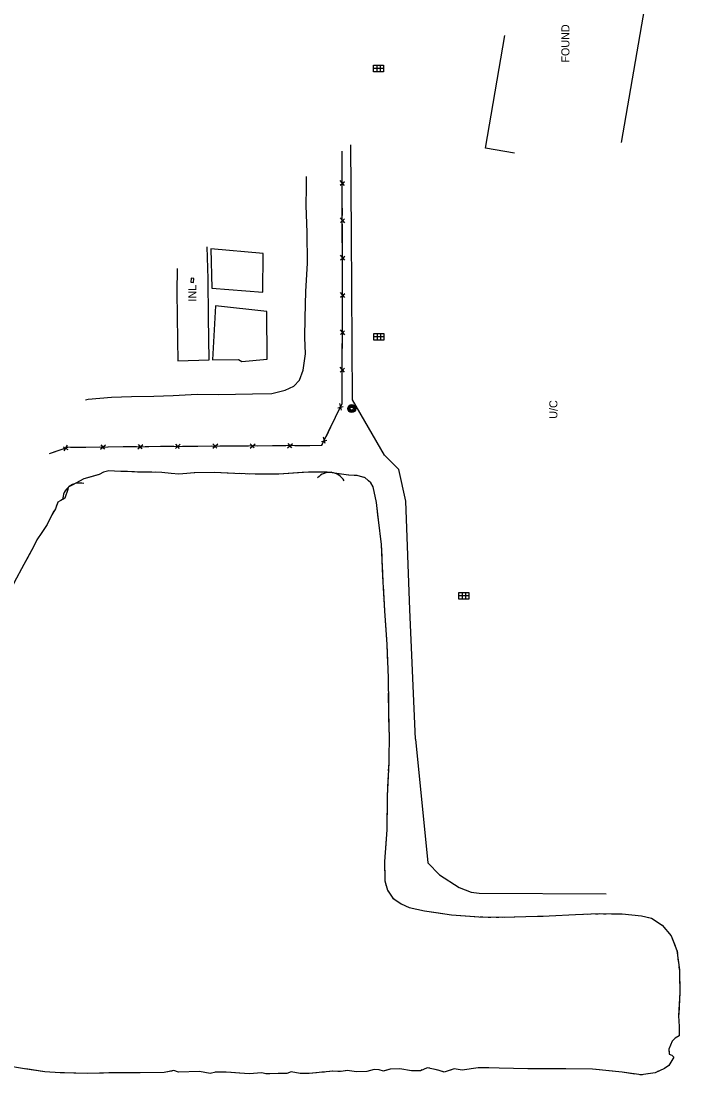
# Model space of a CAD drawing. Extents: x 588843 to 2552415, y 180129 to 269402.
# Drawn here: x 592942 to 593434, y 186354 to 187140 of the extents above; entities that cross this region are included whole.
import ezdxf

# ---------------------------------------------------------------- set-up
doc = ezdxf.new("R2010")
doc.units = 0
for name, color, linetype in [('E_DRN', 7, 'Continuous'), ('E_DRN_PipePlastic', 7, 'Continuous'), ('E_DRN_PipeRein', 7, 'Continuous'), ('Level 12', 7, 'Continuous'), ('Level 15', 7, 'Continuous'), ('Level 16', 7, 'Continuous'), ('Level 17', 7, 'Continuous'), ('Level 19', 7, 'Continuous')]:
    doc.layers.add(name, color=color, linetype=linetype)

msp = doc.modelspace()

# ---------------------------------------------------------------- linework, layer by layer
at = {"layer": 'E_DRN'}
for p, q in [((593205.24, 187101.86), (593205.24, 187106.86)), ((593205.24, 187106.86), (593212.74, 187106.86)), ((593212.74, 187104.36), (593205.24, 187104.36)), ((593207.74, 187106.86), (593207.74, 187101.86)), ((593210.24, 187106.86), (593210.24, 187101.86)), ((593212.74, 187106.86), (593212.74, 187101.86)), ((593212.74, 187101.86), (593205.24, 187101.86)), ((593208.99, 187101.86), (593208.99, 187101.86)), ((593205.52, 186901.87), (593205.52, 186906.87)), ((593205.52, 186906.87), (593213.02, 186906.87)), ((593208.02, 186906.87), (593208.02, 186901.87)), ((593210.52, 186906.87), (593210.52, 186901.87)), ((593213.02, 186906.87), (593213.02, 186901.87)), ((593213.02, 186904.37), (593205.52, 186904.37)), ((593213.02, 186901.87), (593205.52, 186901.87)), ((593209.27, 186901.87), (593209.27, 186901.87)), ((593268.89, 186708.85), (593268.89, 186713.85)), ((593268.89, 186713.85), (593276.39, 186713.85)), ((593276.39, 186711.35), (593268.89, 186711.35)), ((593271.39, 186713.85), (593271.39, 186708.85)), ((593273.89, 186713.85), (593273.89, 186708.85)), ((593276.39, 186713.85), (593276.39, 186708.85)), ((593276.39, 186708.85), (593268.89, 186708.85)), ((593272.64, 186708.85), (593272.64, 186708.85))]:
    msp.add_line(p, q, dxfattribs=at)
at = {"layer": 'E_DRN_PipePlastic'}
for p, q in [((593192.67, 186800.85), (593192.67, 186800.85)), ((593211.66, 186709.2), (593211.66, 186709.2))]:
    msp.add_line(p, q, dxfattribs=at)
at = {"layer": 'E_DRN_PipeRein'}
msp.add_line((593174.13, 186804.34), (593174.13, 186804.34), dxfattribs=at)
at = {"layer": 'Level 12'}
for points in [[(593417.75, 187210.51), (593389.9, 187049.22)], [(593310.3, 187041.33), (593288.69, 187045.06), (593303.2, 187129.12)]]:
    msp.add_lwpolyline(points, dxfattribs=at)
at = {"layer": 'Level 15'}
for p, q in [((593183.67, 187017.33), (593180.43, 187021.04)), ((593180.43, 187017.49), (593183.6, 187020.29)), ((593183.74, 186989.47), (593180.49, 186993.18)), ((593180.5, 186989.63), (593183.66, 186992.44)), ((593183.81, 186961.61), (593180.56, 186965.32)), ((593180.57, 186961.77), (593183.73, 186964.58)), ((593183.87, 186933.74), (593180.64, 186937.47)), ((593180.63, 186933.92), (593183.81, 186936.71)), ((593180.52, 186906.06), (593183.7, 186908.85)), ((593183.75, 186905.88), (593180.53, 186909.61)), ((593180.4, 186878.2), (593183.58, 186880.99)), ((593183.64, 186878.02), (593180.42, 186881.75)), ((593178.55, 186851.43), (593182.62, 186852.57)), ((593181.39, 186849.86), (593180.09, 186854.62)), ((593166.41, 186826.35), (593170.48, 186827.49)), ((593169.25, 186824.79), (593167.96, 186829.54)), ((592973.78, 186822.49), (592977.45, 186820.41)), ((592974.63, 186819.4), (592977.17, 186823.62)), ((593001.79, 186820.67), (593005.47, 186823.94)), ((593001.93, 186823.9), (593004.76, 186820.76)), ((593029.65, 186820.95), (593033.33, 186824.23)), ((593029.78, 186824.19), (593032.61, 186821.05)), ((593057.5, 186821.16), (593061.2, 186824.42)), ((593057.65, 186824.4), (593060.46, 186821.24)), ((593085.36, 186821.33), (593089.06, 186824.59)), ((593085.51, 186824.57), (593088.33, 186821.41)), ((593113.22, 186821.5), (593116.92, 186824.76)), ((593113.37, 186824.74), (593116.18, 186821.58)), ((593141.08, 186821.67), (593144.78, 186824.93)), ((593141.23, 186824.91), (593144.04, 186821.76))]:
    msp.add_line(p, q, dxfattribs=at)
for points in [[(592963.59, 186817.4), (592977.39, 186822.15), (593037.81, 186822.77), (593166.73, 186823.57), (593181.81, 186854.73), (593182.14, 186936.47), (593181.94, 187012.29), (593181.89, 187042.93)], [(593181.9, 187034.07), (593181.89, 187042.93)], [(593181.92, 187022.75), (593181.9, 187034.07)], [(593181.96, 187006.21), (593181.94, 187012.29), (593181.93, 187016.17)], [(593181.98, 186994.89), (593181.96, 187006.21)], [(593182.03, 186978.35), (593182, 186988.31)], [(593182.06, 186967.03), (593182.03, 186978.35)], [(593182.1, 186950.49), (593182.07, 186960.45)], [(593071.18, 186948), (593069.18, 186948.08), (593069.06, 186945.08), (593071.06, 186945), (593071.18, 186948)], [(593182.13, 186939.17), (593182.1, 186950.49)], [(593182.08, 186922.63), (593182.12, 186932.59)], [(593182.04, 186911.31), (593182.08, 186922.63)], [(593181.97, 186894.77), (593182.01, 186904.73)], [(593181.93, 186883.45), (593181.97, 186894.77)], [(593181.86, 186866.91), (593181.9, 186876.87)], [(593181.81, 186855.59), (593181.86, 186866.91)], [(593174.98, 186840.61), (593179.32, 186849.58)], [(593170.05, 186830.43), (593174.98, 186840.61)], [(592963.59, 186817.4), (592973.01, 186820.64)], [(592979.33, 186822.17), (592990.66, 186822.29)], [(592990.66, 186822.29), (593000.61, 186822.39)], [(593007.19, 186822.46), (593018.51, 186822.58)], [(593018.51, 186822.58), (593028.47, 186822.68)], [(593035.05, 186822.75), (593037.81, 186822.77), (593046.37, 186822.83)], [(593046.37, 186822.83), (593056.33, 186822.89)], [(593062.91, 186822.93), (593074.23, 186823)], [(593074.23, 186823), (593084.19, 186823.06)], [(593090.77, 186823.1), (593102.09, 186823.17)], [(593102.09, 186823.17), (593112.05, 186823.23)], [(593118.63, 186823.27), (593129.95, 186823.34)], [(593129.95, 186823.34), (593139.91, 186823.4)], [(593146.49, 186823.44), (593157.81, 186823.51)], [(593157.81, 186823.51), (593166.73, 186823.57), (593167.18, 186824.5)]]:
    msp.add_lwpolyline(points, dxfattribs=at)
for centre, start, end in [((593172.56, 186790.78), 29.98007, 136.21963), ((592985.97, 186782.95), 74.38032, 180.61989)]:
    msp.add_arc(centre, 12.5, start, end, dxfattribs=at)
at = {"layer": 'Level 16'}
for centre, radius in [((593188.99, 186850.91), 3), ((593188.99, 186850.91), 2.43), ((593188.98, 186850.88), 1.94), ((593188.93, 186850.87), 1.21)]:
    msp.add_circle(centre, radius, dxfattribs=at)
at = {"layer": 'Level 17'}
for points in [[(593236.56, 186604.57), (593232.23, 186701.05), (593229.21, 186781.81), (593224.03, 186805.6), (593213.35, 186816.17), (593189.6, 186857.42), (593188.88, 186981.32), (593188.27, 187047.46)], [(592990.42, 186857.43), (592992.54, 186857.9), (593009.9, 186859.52), (593024.84, 186859.98), (593041.36, 186860.14), (593055.85, 186860.73), (593073.84, 186861.57), (593089.58, 186861.5), (593115.05, 186862.03), (593129.37, 186862.17), (593139.27, 186864.57), (593145.93, 186867.69), (593149.94, 186872.24), (593152.8, 186879.52), (593154.48, 186891.67), (593154.05, 186903.98), (593154.38, 186918.67), (593154.81, 186938.29), (593155.99, 186959.28), (593155.71, 186982.25), (593154.96, 187002.3), (593155.23, 187015.75), (593155.17, 187023.94)], [(593058.73, 186955.42), (593058.71, 186937.78), (593059.01, 186901.83), (593059.46, 186886.51), (593082.72, 186887.2), (593082.32, 186918.9), (593081.87, 186947.63), (593081.24, 186971.41)], [(593084.69, 186940.68), (593122.75, 186937.61), (593122.84, 186966.61), (593083.99, 186970.05), (593084.69, 186940.68)], [(593085.17, 186887.24), (593104.68, 186887.55), (593107.1, 186886.13), (593125.9, 186887.8), (593125.67, 186923.22), (593087.52, 186927.64), (593085.17, 186887.24)], [(593236.56, 186604.57), (593245.76, 186512.24), (593254.4, 186503.26), (593269.01, 186493.96), (593277.98, 186490.3), (593283.96, 186489.63), (593378.71, 186489.09)]]:
    msp.add_lwpolyline(points, dxfattribs=at)
at = {"layer": 'Level 19'}
for points in [[(593216.86, 186609.81), (593216.32, 186650.11), (593215.3, 186675.06), (593213.71, 186700.12), (593212.25, 186726.11), (593211.2, 186749.52), (593208.96, 186767.97), (593207.37, 186781.01), (593204.86, 186792.6), (593203.23, 186795.53), (593199.06, 186799.33), (593192.99, 186801.04), (593186.45, 186801.32), (593177.78, 186802.54), (593170.76, 186803.62), (593156.87, 186803.62), (593134.52, 186802.04), (593117.29, 186802.02), (593101.88, 186802.53), (593086.65, 186803.22), (593071.63, 186802.94), (593065.95, 186802.46), (593060.14, 186802.15), (593054.48, 186802.59), (593047.5, 186803.38), (593039.95, 186803.43), (593029.4, 186803.56), (593021.84, 186804.03), (593016.93, 186803.93), (593012.17, 186804.27), (593007.83, 186804.54), (593003.86, 186803.43), (593000.7, 186801.89), (592989.31, 186798.53), (592980.58, 186793.78), (592977.68, 186792.4), (592977.36, 186790.49), (592975.05, 186784.07), (592969.98, 186781.15), (592968.03, 186776.23), (592965.54, 186771.75), (592961.84, 186764.5), (592957.97, 186758.51), (592954.27, 186753.11), (592951.88, 186748.48), (592944.56, 186734.79), (592937.33, 186721.35)], [(593021.09, 186804.02), (593016.93, 186803.93), (593012.17, 186804.27), (593007.83, 186804.54), (593003.86, 186803.43), (593000.7, 186801.89), (592992.95, 186799.6)], [(592992.95, 186799.6), (592989.31, 186798.53), (592980.58, 186793.78), (592977.68, 186792.4), (592977.36, 186790.49), (592975.05, 186784.07), (592972.19, 186782.42)], [(593027.08, 186803.7), (593025.08, 186803.83)], [(593033.07, 186803.51), (593031.07, 186803.54)], [(593039.07, 186803.44), (593037.07, 186803.46)], [(593071.98, 186802.95), (593071.63, 186802.94), (593065.95, 186802.46), (593060.14, 186802.15), (593054.48, 186802.59), (593047.5, 186803.38), (593043.07, 186803.41)], [(593100.96, 186802.57), (593086.65, 186803.22), (593071.98, 186802.95)], [(593106.96, 186802.36), (593104.96, 186802.43)], [(593112.95, 186802.16), (593110.96, 186802.23)], [(593118.95, 186802.02), (593117.29, 186802.02), (593116.95, 186802.03)], [(593151.91, 186803.27), (593134.52, 186802.04), (593122.95, 186802.03)], [(593180.79, 186802.12), (593177.78, 186802.54), (593170.76, 186803.62), (593156.87, 186803.62), (593151.91, 186803.27)], [(593186.73, 186801.3), (593186.45, 186801.32), (593184.75, 186801.56)], [(593192.72, 186801.05), (593190.72, 186801.13)], [(593198.51, 186799.48), (593196.58, 186800.02)], [(593208.78, 186769.52), (593207.37, 186781.01), (593204.86, 186792.6), (593203.23, 186795.53), (593201.59, 186797.02)], [(592966.98, 186774.34), (592966.01, 186772.6)], [(592969.45, 186779.8), (592968.71, 186777.94)], [(592964.16, 186769.05), (592963.25, 186767.27)], [(593211.6, 186740.68), (593211.2, 186749.52), (593208.96, 186767.97), (593208.78, 186769.52)], [(592961.36, 186763.75), (592957.97, 186758.51), (592954.27, 186753.11), (592951.88, 186748.48), (592946.69, 186738.77)], [(592946.69, 186738.77), (592944.56, 186734.79), (592937.33, 186721.35), (592933.82, 186712.99), (592933.73, 186712.86)], [(593211.87, 186734.68), (593211.78, 186736.68)], [(593212.14, 186728.69), (593212.05, 186730.69)], [(593212.45, 186722.7), (593212.33, 186724.69)], [(593214.37, 186689.75), (593213.71, 186700.12), (593212.67, 186718.7)], [(593215.88, 186660.79), (593215.3, 186675.06), (593214.37, 186689.75)], [(593216.13, 186654.8), (593216.05, 186656.8)], [(593216.34, 186648.8), (593216.32, 186650.11), (593216.29, 186650.8)], [(593216.42, 186642.8), (593216.39, 186644.8)], [(593216.86, 186609.81), (593216.47, 186638.8)], [(593216.86, 186609.81), (593216.56, 186586.95), (593215.32, 186562.25), (593215.05, 186536.77), (593213.45, 186513.35), (593213.65, 186498.8), (593215.61, 186491.81), (593219.7, 186486.03), (593225.79, 186481.66), (593231.86, 186479), (593243.12, 186476.52), (593263.24, 186473.46), (593283.71, 186471.96), (593301.11, 186471.69), (593318.8, 186472.36), (593336.23, 186472.73), (593355.81, 186473.82), (593373.45, 186474.41), (593390.65, 186474.28), (593404.97, 186472.78), (593412.33, 186471.02), (593420.33, 186465.87), (593427.13, 186457.82), (593431.42, 186447.02), (593433.21, 186432.41), (593433.64, 186415.5), (593432.66, 186398.29), (593433.04, 186390.38), (593432.95, 186383.35), (593430.06, 186381.5), (593429.61, 186381.08)], [(593216.86, 186609.81), (593216.56, 186586.95), (593216.25, 186580.82)], [(593216.05, 186576.82), (593215.95, 186574.82)], [(593215.75, 186570.83), (593215.65, 186568.83)], [(593215.45, 186564.84), (593215.35, 186562.84)], [(593215.28, 186558.84), (593215.05, 186536.77), (593214.58, 186529.86)], [(593214.58, 186529.86), (593213.45, 186513.35), (593213.62, 186500.9)], [(593214.16, 186496.97), (593214.7, 186495.04)], [(593215.98, 186491.29), (593217.14, 186489.65)], [(593219.44, 186486.38), (593219.7, 186486.03), (593220.97, 186485.12)], [(593224.22, 186482.79), (593225.79, 186481.66), (593231.86, 186479), (593243.12, 186476.52), (593251.93, 186475.18)], [(593251.93, 186475.18), (593263.24, 186473.46), (593280.75, 186472.17)], [(593331.72, 186472.63), (593336.23, 186472.73), (593355.81, 186473.82), (593360.69, 186473.98)], [(593364.69, 186474.12), (593366.69, 186474.18)], [(593370.68, 186474.32), (593372.68, 186474.38)], [(593376.68, 186474.38), (593378.68, 186474.37)], [(593382.68, 186474.34), (593390.65, 186474.28), (593404.97, 186472.78), (593411.42, 186471.23)], [(593284.74, 186471.94), (593286.74, 186471.91)], [(593290.74, 186471.85), (593292.74, 186471.82)], [(593296.74, 186471.76), (593298.74, 186471.73)], [(593302.74, 186471.76), (593318.8, 186472.36), (593331.72, 186472.63)], [(593411.42, 186471.23), (593412.33, 186471.02), (593420.33, 186465.87), (593427.13, 186457.82), (593430.09, 186450.37)], [(593431.47, 186446.62), (593431.71, 186444.64)], [(593432.2, 186440.67), (593432.44, 186438.68)], [(593432.93, 186434.71), (593433.17, 186432.73)], [(593433.3, 186428.73), (593433.64, 186415.5), (593432.74, 186399.76)], [(593432.74, 186399.76), (593432.66, 186398.29), (593433.04, 186390.38), (593432.95, 186383.35), (593430.06, 186381.5), (593429.85, 186381.31)], [(593429.61, 186381.08), (593427.75, 186379.32), (593425.35, 186373.29), (593425.65, 186369.71), (593427.6, 186368.81), (593429.04, 186367.45), (593425.33, 186361.3), (593422.04, 186358.91), (593415.29, 186355.85), (593404.82, 186354.17), (593390.53, 186356.12), (593368.47, 186358.41), (593348.67, 186358.65), (593320.54, 186358.8), (593298.99, 186359.29), (593283.19, 186359.4), (593271.35, 186357.63), (593265.33, 186358.73), (593257.95, 186356.27), (593253.33, 186357.66), (593245.1, 186359.58), (593240.14, 186357.15), (593233.53, 186357.21), (593224.87, 186358.77), (593217.67, 186358.57), (593212.73, 186356.99), (593209.42, 186357.99), (593205.61, 186358.28), (593200.33, 186356.81), (593192.61, 186356.43), (593185.49, 186357.41), (593181.04, 186356.76), (593174.82, 186356.93), (593157.24, 186355.25), (593150.65, 186355.17), (593143.76, 186356.52), (593140.51, 186355.3), (593127.83, 186354.98), (593124.85, 186354.9), (593121.88, 186355.7), (593112.54, 186354.89), (593095.26, 186356.21), (593087.65, 186356.23), (593083.37, 186355.23), (593075.52, 186356.74), (593059.85, 186356.3), (593056.39, 186357.42), (593049.1, 186355.95), (593031.26, 186355.72), (593009.88, 186355.69), (592991.69, 186355.3), (592971.7, 186355.7), (592960.25, 186356.56), (592944.93, 186358.75), (592930.29, 186361.23)], [(593427.83, 186379.39), (593427.75, 186379.32), (593425.35, 186373.29), (593425.55, 186370.88)], [(593425.62, 186370.07), (593425.65, 186369.71), (593427.6, 186368.81), (593429.04, 186367.45), (593425.33, 186361.3), (593422.04, 186358.91), (593421.15, 186358.51)], [(592974.83, 186355.64), (592971.7, 186355.7), (592960.25, 186356.56), (592946.01, 186358.6)], [(593054.71, 186357.08), (593049.1, 186355.95), (593031.26, 186355.72), (593025.82, 186355.71)], [(593083.35, 186355.24), (593075.52, 186356.74), (593059.85, 186356.3), (593056.39, 186357.42), (593054.71, 186357.08)], [(593089.24, 186356.23), (593087.65, 186356.23), (593087.25, 186356.14)], [(593095.24, 186356.21), (593093.24, 186356.21)], [(593162.66, 186355.77), (593157.24, 186355.25), (593150.65, 186355.17), (593143.76, 186356.52), (593140.51, 186355.3), (593134.04, 186355.14)], [(593168.64, 186356.34), (593166.65, 186356.15)], [(593174.61, 186356.91), (593172.62, 186356.72)], [(593180.61, 186356.77), (593178.61, 186356.82)], [(593213.1, 186357.11), (593212.73, 186356.99), (593209.42, 186357.99), (593205.61, 186358.28), (593200.33, 186356.81), (593192.61, 186356.43), (593185.49, 186357.41), (593184.57, 186357.27)], [(593241.57, 186357.86), (593240.14, 186357.15), (593233.53, 186357.21), (593224.87, 186358.77), (593217.67, 186358.57), (593213.1, 186357.11)], [(593247.12, 186359.11), (593245.17, 186359.57)], [(593252.96, 186357.75), (593251.01, 186358.2)], [(593258.7, 186356.52), (593257.95, 186356.27), (593256.8, 186356.62)], [(593291.11, 186359.34), (593283.19, 186359.4), (593271.35, 186357.63), (593265.33, 186358.73), (593262.5, 186357.79)], [(593320.11, 186358.81), (593298.99, 186359.29), (593291.11, 186359.34)], [(593326.11, 186358.77), (593324.11, 186358.78)], [(593332.11, 186358.74), (593330.11, 186358.75)], [(593338.11, 186358.71), (593336.11, 186358.72)], [(593371.09, 186358.14), (593368.47, 186358.41), (593348.67, 186358.65), (593342.11, 186358.69)], [(593399.9, 186354.84), (593390.53, 186356.12), (593371.09, 186358.14)], [(593417.5, 186356.85), (593415.68, 186356.03)], [(593003.82, 186355.56), (592991.69, 186355.3), (592974.83, 186355.64)], [(593009.82, 186355.69), (593007.82, 186355.65)], [(593015.82, 186355.7), (593013.82, 186355.7)], [(593021.82, 186355.71), (593019.82, 186355.71)], [(593101.22, 186355.76), (593099.22, 186355.91)], [(593134.04, 186355.14), (593127.83, 186354.98), (593124.85, 186354.9), (593121.88, 186355.7), (593112.54, 186354.89), (593105.21, 186355.45)], [(593405.84, 186354.34), (593404.82, 186354.17), (593403.86, 186354.3)], [(593411.77, 186355.28), (593409.79, 186354.97)]]:
    msp.add_lwpolyline(points, dxfattribs=at)

# ---------------------------------------------------------------- texts
at = {"layer": 'Level 12'}
msp.add_text('FOUND', height=6, rotation=90, dxfattribs=at).set_placement((593351.26, 187108.85))
at = {"layer": 'Level 15'}
msp.add_text('INL', height=6, rotation=90, dxfattribs=at).set_placement((593073.09, 186930.73))
at = {"layer": 'Level 17'}
msp.add_text('U/C', height=6, rotation=90, dxfattribs=at).set_placement((593342.29, 186843.34))

doc.saveas('drawing.dxf')
